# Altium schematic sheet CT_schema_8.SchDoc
size 277 x 170 mm
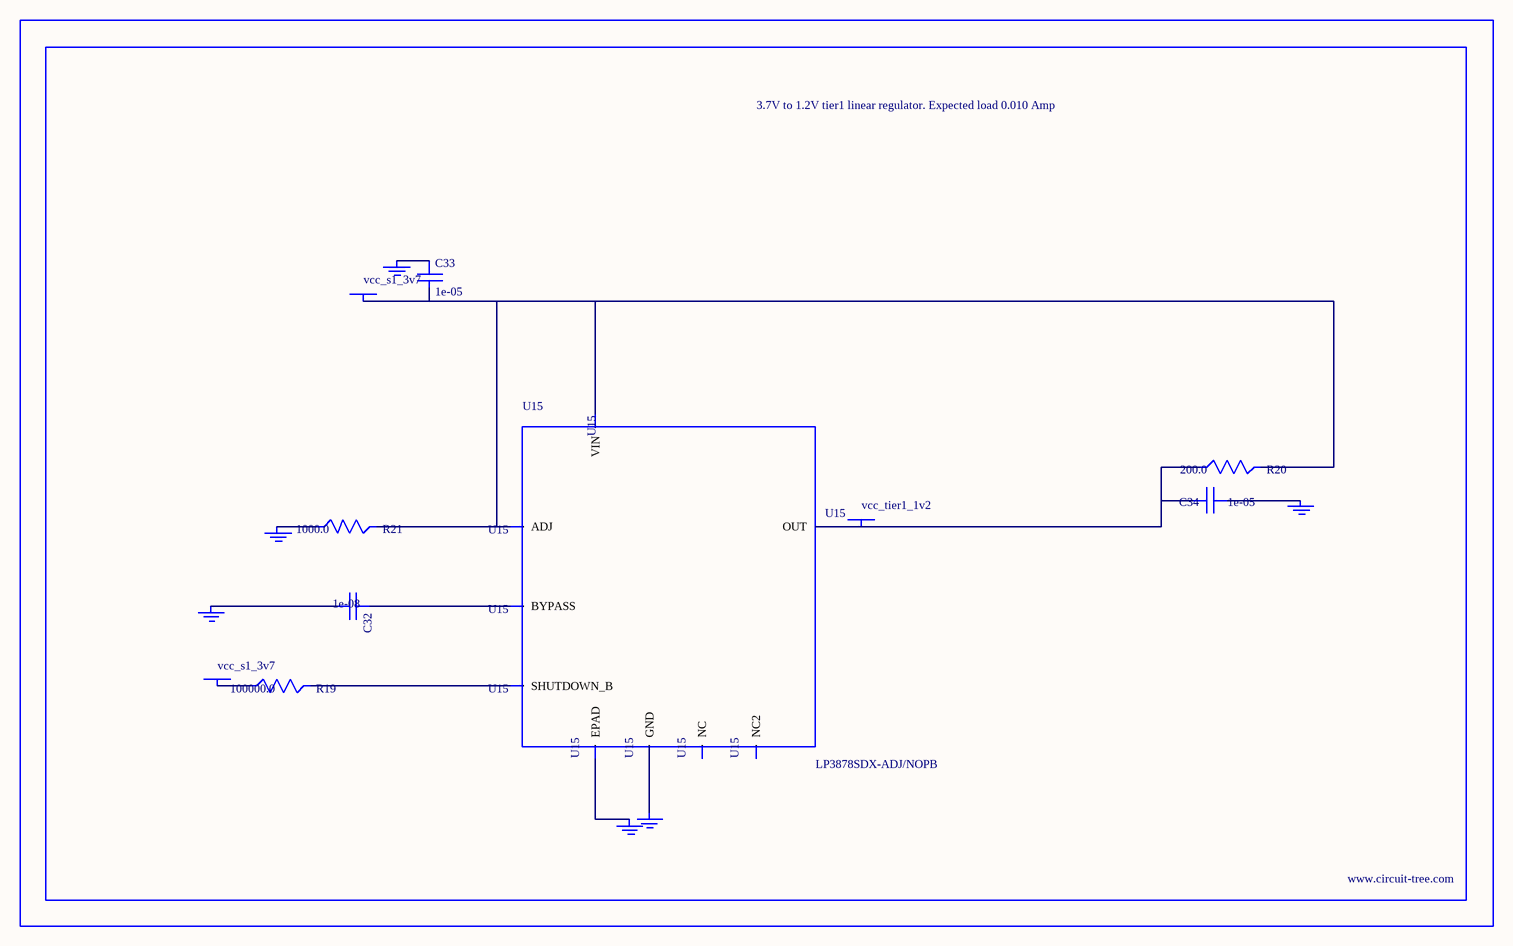
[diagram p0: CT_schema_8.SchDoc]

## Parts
BORDER7  (no value)
C32  1e-08  [C0402]
C33  1e-05  [C0805]
C34  1e-05  [C0805]
GND_INSTANCE_7_0  (no value)
GND_INSTANCE_7_1  (no value)
GND_INSTANCE_7_2  (no value)
GND_INSTANCE_7_3  (no value)
GND_INSTANCE_7_4  (no value)
GND_INSTANCE_7_5  (no value)
POWER_INSTANCE_7_0  vcc_s1_3v7
POWER_INSTANCE_7_1  vcc_s1_3v7
POWER_INSTANCE_7_2  vcc_tier1_1v2
R19  100000.0  [R0603]
R20  200.0  [R0603]
R21  1000.0  [R0603]
U15  LP3878SDX-ADJ/NOPB  [WSON-8]

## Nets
NetC32_1: C32.1 U15.1(BYPASS)
NetC32_2: C32.2 GND_INSTANCE_7_0.0(GND)
NetC33_1: C33.1 GND_INSTANCE_7_1.0(GND)
NetC33_2: C33.2 POWER_INSTANCE_7_0.0(PWR) R20.2 R21.2 U15.4(VIN) U15.6(ADJ)
NetC34_1: C34.1 GND_INSTANCE_7_2.0(GND)
NetC34_2: C34.2 POWER_INSTANCE_7_2.0(PWR) R20.1 U15.5(OUT)
NetGND_INSTANCE_7_3_0: GND_INSTANCE_7_3.0(GND) R21.1
NetGND_INSTANCE_7_4_0: GND_INSTANCE_7_4.0(GND) U15.PAD(EPAD)
NetGND_INSTANCE_7_5_0: GND_INSTANCE_7_5.0(GND) U15.3(GND)
NetPOWER_INSTANCE_7_1_0: POWER_INSTANCE_7_1.0(PWR) R19.1
NetR19_2: R19.2 U15.8(SHUTDOWN_B)

Not connected (* = marked no-connect by the designer): U15 2(NC) 7(NC2)

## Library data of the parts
BORDER7 = BORDER_PAGE7
C32 = C0402C103K3RAC
C33 = C0805C106K8RACTU
C34 = GRM219R60J106ME19D
GND_INSTANCE_7_0-GND_INSTANCE_7_5 = GND
POWER_INSTANCE_7_0-POWER_INSTANCE_7_2 = PWR
R19 = RC0603JR-07100KL
R20 = RC0603JR-07200RL
R21 = RC0603JR-071KL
